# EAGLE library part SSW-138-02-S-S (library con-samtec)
THROUGH-HOLE .025" SQ POST SOCKET Source: Samtec SSW.pdf
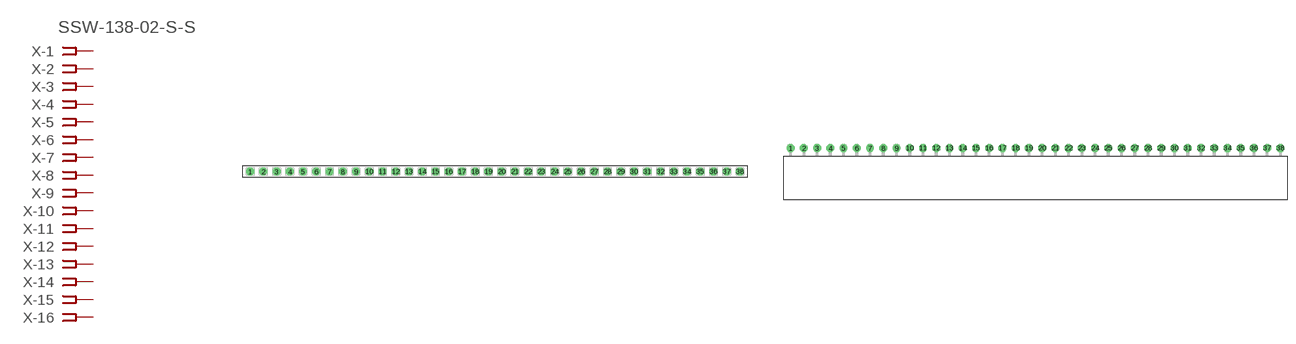
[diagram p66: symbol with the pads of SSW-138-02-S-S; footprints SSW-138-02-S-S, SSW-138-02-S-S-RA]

Designator prefix X; gates -1=FPINV -2=FPIN -3=FPIN -4=FPIN -5=FPIN -6=FPIN -7=FPIN -8=FPIN -9=FPIN -10=FPIN -11=FPIN -12=FPIN -13=FPIN -14=FPIN -15=FPIN -16=FPIN -17=FPIN -18=FPIN -19=FPIN -20=FPIN -21=FPIN -22=FPIN -23=FPIN -24=FPIN -25=FPIN -26=FPIN -27=FPIN -28=FPIN -29=FPIN -30=FPIN -31=FPIN -32=FPIN -33=FPIN -34=FPIN -35=FPIN -36=FPIN -37=FPIN -38=FPIN

## SSW-138-02-S-S (MPN: SSW-138-02-S-S; OC_FARNELL: unknown; OC_NEWARK: 11P9930)  [SSW-138-02-S-S]
1  -1:1  pas
2  -2:1  pas
3  -3:1  pas
4  -4:1  pas
5  -5:1  pas
6  -6:1  pas
7  -7:1  pas
8  -8:1  pas
9  -9:1  pas
10  -10:1  pas
11  -11:1  pas
12  -12:1  pas
13  -13:1  pas
14  -14:1  pas
15  -15:1  pas
16  -16:1  pas
17  -17:1  pas
18  -18:1  pas
19  -19:1  pas
20  -20:1  pas
21  -21:1  pas
22  -22:1  pas
23  -23:1  pas
24  -24:1  pas
25  -25:1  pas
26  -26:1  pas
27  -27:1  pas
28  -28:1  pas
29  -29:1  pas
30  -30:1  pas
31  -31:1  pas
32  -32:1  pas
33  -33:1  pas
34  -34:1  pas
35  -35:1  pas
36  -36:1  pas
37  -37:1  pas
38  -38:1  pas

## SSW-138-02-S-S-RA (OC_FARNELL: unknown; OC_NEWARK: unknown)  [SSW-138-02-S-S-RA]
Pads as for SSW-138-02-S-S

## Footprint SSW-138-02-S-S (pad centres in mm)
THROUGH-HOLE .025" SQ POST SOCKET Source: Samtec SSW.pdf
drill 1 pad 1.5 octagon: 1 -46.99,0; 2 -44.45,0; 3 -41.91,0; 4 -39.37,0; 5 -36.83,0; 6 -34.29,0; 7 -31.75,0; 8 -29.21,0; 9 -26.67,0; 10 -24.13,0; 11 -21.59,0; 12 -19.05,0; 13 -16.51,0; 14 -13.97,0; 15 -11.43,0; 16 -8.89,0; 17 -6.35,0; 18 -3.81,0; 19 -1.27,0; 20 1.27,0; 21 3.81,0; 22 6.35,0; 23 8.89,0; 24 11.43,0; 25 13.97,0; 26 16.51,0; 27 19.05,0; 28 21.59,0; 29 24.13,0; 30 26.67,0; 31 29.21,0; 32 31.75,0; 33 34.29,0; 34 36.83,0; 35 39.37,0; 36 41.91,0; 37 44.45,0; 38 46.99,0

## Footprint SSW-138-02-S-S-RA (pad centres in mm)
THROUGH-HOLE .025" SQ POST SOCKET Source: Samtec SSW.pdf
drill 1 pad 1.5 octagon: 1 -46.99,1.524; 2 -44.45,1.524; 3 -41.91,1.524; 4 -39.37,1.524; 5 -36.83,1.524; 6 -34.29,1.524; 7 -31.75,1.524; 8 -29.21,1.524; 9 -26.67,1.524; 10 -24.13,1.524; 11 -21.59,1.524; 12 -19.05,1.524; 13 -16.51,1.524; 14 -13.97,1.524; 15 -11.43,1.524; 16 -8.89,1.524; 17 -6.35,1.524; 18 -3.81,1.524; 19 -1.27,1.524; 20 1.27,1.524; 21 3.81,1.524; 22 6.35,1.524; 23 8.89,1.524; 24 11.43,1.524; 25 13.97,1.524; 26 16.51,1.524; 27 19.05,1.524; 28 21.59,1.524; 29 24.13,1.524; 30 26.67,1.524; 31 29.21,1.524; 32 31.75,1.524; 33 34.29,1.524; 34 36.83,1.524; 35 39.37,1.524; 36 41.91,1.524; 37 44.45,1.524; 38 46.99,1.524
